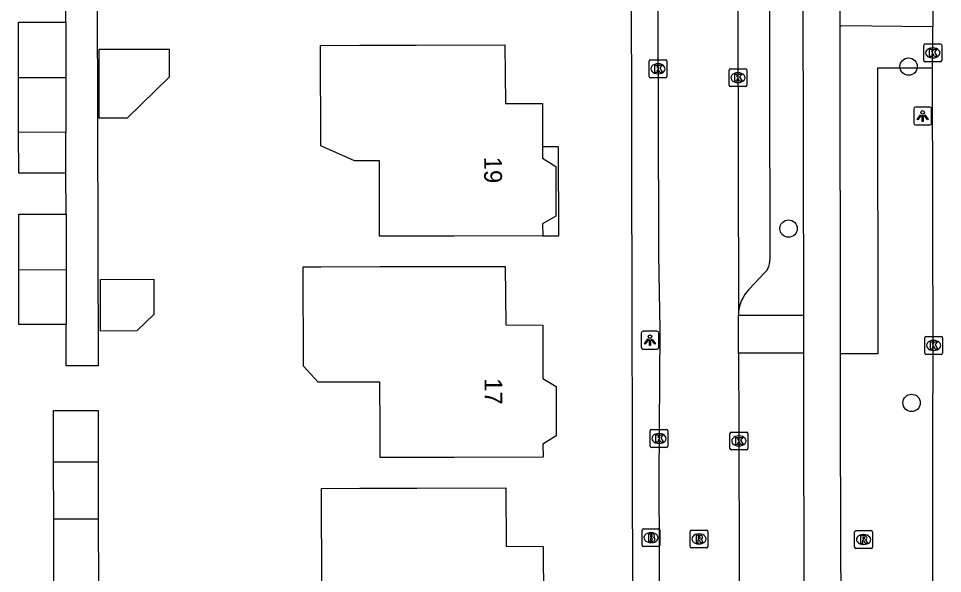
# Model space of a CAD drawing. Extents: x 160457 to 162082, y 388340 to 389736.
# Drawn here: x 160980.8 to 161032.8, y 388491.8 to 388523.1 of the extents above; entities that cross this region are included whole.
import ezdxf

# ---------------------------------------------------------------- set-up
doc = ezdxf.new("R2010")
doc.units = 0
for name, color, linetype in [('IMGEO_Boom', 7, 'Continuous'), ('IMGEO_Brandkraan', 7, 'Continuous'), ('IMGEO_Fietspad_gesloten', 7, 'Continuous'), ('IMGEO_Fietspad_open', 7, 'Continuous'), ('IMGEO_Kolk', 7, 'Continuous'), ('IMGEO_Lichtpunt', 7, 'Continuous'), ('IMGEO_Pand', 7, 'Continuous'), ('IMGEO_Pand_nummerreeks', 7, 'Continuous'), ('IMGEO_Pand_overbouw', 7, 'Continuous'), ('IMGEO_Parkeervlak_open', 7, 'Continuous'), ('IMGEO_Rijbaan_lokaal_gesloten', 7, 'Continuous'), ('IMGEO_Rijbaan_lokaal_open', 7, 'Continuous'), ('IMGEO_Rioolput', 7, 'Continuous'), ('IMGEO_Voetpad_open', 7, 'Continuous')]:
    doc.layers.add(name, color=color, linetype=linetype)

msp = doc.modelspace()

# ---------------------------------------------------------------- linework, layer by layer
at = {"layer": 'IMGEO_Boom'}
for centre in [(161030.855, 388520.352), (161024.103, 388511.242), (161031.022, 388501.444)]:
    msp.add_circle(centre, 0.489, dxfattribs=at)
at = {"layer": 'IMGEO_Brandkraan'}
for p, q in [((161015.872, 388493.436), (161015.872, 388494.288)), ((161015.947, 388494.362), (161016.799, 388494.362)), ((161016.36, 388494.142), (161016.385, 388494.142)), ((161016.873, 388494.288), (161016.873, 388493.436)), ((161016.799, 388493.362), (161015.947, 388493.362)), ((161016.383, 388493.582), (161016.358, 388493.582))]:
    msp.add_line(p, q, dxfattribs=at)
for points in [[(161015.872, 388493.436), (161015.872, 388494.288)], [(161015.947, 388494.362), (161016.799, 388494.362)], [(161016.873, 388494.288), (161016.873, 388493.436)], [(161016.22, 388494.062), (161016.22, 388493.662), (161016.433, 388493.662)], [(161016.451, 388494.062), (161016.22, 388494.062)], [(161016.399, 388493.981), (161016.345, 388493.981), (161016.345, 388493.905)], [(161016.345, 388493.905), (161016.398, 388493.905)], [(161016.407, 388493.829), (161016.345, 388493.829), (161016.345, 388493.748)], [(161016.345, 388493.748), (161016.407, 388493.748)], [(161016.799, 388493.362), (161015.947, 388493.362)]]:
    msp.add_lwpolyline(points, dxfattribs=at)
for centre, radius, start, end in [((161015.949, 388494.286), 0.0765, 91.552, 178.448), ((161015.949, 388494.286), 0.0765, 91.552, 178.448), ((161016.797, 388494.286), 0.0765, 1.552, 88.448), ((161016.797, 388494.286), 0.0765, 1.552, 88.448), ((161016.4, 388493.943), 0.0379, 267.8285, 90.9355), ((161016.408, 388493.788), 0.0404, 269.8759, 90.5077), ((161016.439, 388493.913), 0.251, 268.6676, 293.5347), ((161016.455, 388493.917), 0.145, 59.4692, 91.5367), ((161016.48, 388493.964), 0.0922, 285.5137, 58.1501), ((161016.485, 388493.772), 0.105, 301.3115, 78.989), ((161015.949, 388493.438), 0.0765, 181.552, 268.448), ((161015.949, 388493.438), 0.0765, 181.552, 268.448), ((161016.797, 388493.438), 0.0765, 271.552, 358.448), ((161016.797, 388493.438), 0.0765, 271.552, 358.448)]:
    msp.add_arc(centre, radius, start, end, dxfattribs=at)
for centre, major_axis, ratio, start_param, end_param in [((161016.359, 388493.862), (-0.387, 0.002), 0.722429, 4.712389, 7.853982), ((161016.384, 388493.862), (-0.39, 0.002), 0.717154, 1.570796, 4.712389)]:
    msp.add_ellipse(centre, major_axis=major_axis, ratio=ratio, start_param=start_param, end_param=end_param, dxfattribs=at)
at = {"layer": 'IMGEO_Fietspad_gesloten'}
for points in [[(161024.704, 388621.181), (161024.714, 388616.416), (161024.95, 388506.373)], [(161027, 388522.588), (161026.975, 388527.496)], [(161027.02, 388504.221), (161027, 388522.563), (161027, 388522.588)], [(161024.95, 388506.373), (161024.943, 388504.232)], [(161024.943, 388504.232), (161024.953, 388500), (161025.043, 388462.172)], [(161027.148, 388462.179), (161027.033, 388500), (161027.02, 388504.221)]]:
    msp.add_lwpolyline(points, dxfattribs=at)
at = {"layer": 'IMGEO_Fietspad_open'}
msp.add_lwpolyline([(161032.211, 388522.593), (161027.085, 388522.641), (161027.05, 388522.642)], dxfattribs=at)
msp.add_arc((161027.057, 388522.585), 0.0572, 97.1712, 177.234, dxfattribs=at)
at = {"layer": 'IMGEO_Kolk'}
for p, q in [((161031.714, 388520.698), (161031.714, 388521.55)), ((161031.789, 388521.624), (161032.641, 388521.624)), ((161032.202, 388521.404), (161032.227, 388521.404)), ((161032.715, 388521.55), (161032.715, 388520.698)), ((161016.265, 388519.803), (161016.265, 388520.655)), ((161016.34, 388520.729), (161017.192, 388520.729)), ((161017.266, 388520.655), (161017.266, 388519.803)), ((161032.225, 388520.844), (161032.2, 388520.844)), ((161016.753, 388520.509), (161016.778, 388520.509)), ((161020.755, 388519.304), (161020.755, 388520.156)), ((161020.83, 388520.23), (161021.682, 388520.23)), ((161021.756, 388520.156), (161021.756, 388519.304)), ((161032.641, 388520.624), (161031.789, 388520.624)), ((161017.192, 388519.729), (161016.34, 388519.729)), ((161016.776, 388519.949), (161016.751, 388519.949)), ((161021.243, 388520.01), (161021.268, 388520.01)), ((161021.682, 388519.23), (161020.83, 388519.23)), ((161021.266, 388519.45), (161021.241, 388519.45)), ((161031.761, 388504.246), (161031.761, 388505.098)), ((161031.836, 388505.172), (161032.688, 388505.172)), ((161032.762, 388505.098), (161032.762, 388504.246)), ((161032.249, 388504.952), (161032.274, 388504.952)), ((161032.688, 388504.172), (161031.836, 388504.172)), ((161032.272, 388504.392), (161032.247, 388504.392)), ((161016.322, 388499.014), (161016.322, 388499.866)), ((161016.397, 388499.94), (161017.249, 388499.94)), ((161017.323, 388499.866), (161017.323, 388499.014)), ((161016.81, 388499.72), (161016.835, 388499.72)), ((161020.81, 388498.878), (161020.81, 388499.73)), ((161020.885, 388499.804), (161021.737, 388499.804)), ((161021.298, 388499.584), (161021.323, 388499.584)), ((161021.811, 388499.73), (161021.811, 388498.878)), ((161017.249, 388498.94), (161016.397, 388498.94)), ((161016.833, 388499.16), (161016.808, 388499.16)), ((161021.321, 388499.024), (161021.296, 388499.024)), ((161021.737, 388498.804), (161020.885, 388498.804))]:
    msp.add_line(p, q, dxfattribs=at)
for points in [[(161031.714, 388520.698), (161031.714, 388521.55)], [(161031.789, 388521.624), (161032.641, 388521.624)], [(161032.035, 388521.324), (161032.158, 388521.324), (161032.158, 388521.173), (161032.288, 388521.324), (161032.452, 388521.324), (161032.306, 388521.173), (161032.459, 388520.924), (161032.307, 388520.924), (161032.222, 388521.088), (161032.158, 388521.021), (161032.158, 388520.924), (161032.035, 388520.924), (161032.035, 388521.324)], [(161032.715, 388521.55), (161032.715, 388520.698)], [(161016.265, 388519.803), (161016.265, 388520.655)], [(161016.34, 388520.729), (161017.192, 388520.729)], [(161017.266, 388520.655), (161017.266, 388519.803)], [(161016.586, 388520.429), (161016.709, 388520.429), (161016.709, 388520.278), (161016.839, 388520.429), (161017.003, 388520.429), (161016.857, 388520.278), (161017.01, 388520.029), (161016.858, 388520.029), (161016.773, 388520.193), (161016.709, 388520.126), (161016.709, 388520.029), (161016.586, 388520.029), (161016.586, 388520.429)], [(161020.755, 388519.304), (161020.755, 388520.156)], [(161020.83, 388520.23), (161021.682, 388520.23)], [(161021.756, 388520.156), (161021.756, 388519.304)], [(161032.641, 388520.624), (161031.789, 388520.624)], [(161017.192, 388519.729), (161016.34, 388519.729)], [(161021.076, 388519.93), (161021.199, 388519.93), (161021.199, 388519.779), (161021.329, 388519.93), (161021.493, 388519.93), (161021.347, 388519.779), (161021.5, 388519.53), (161021.348, 388519.53), (161021.263, 388519.694), (161021.199, 388519.627), (161021.199, 388519.53), (161021.076, 388519.53), (161021.076, 388519.93)], [(161021.682, 388519.23), (161020.83, 388519.23)], [(161031.761, 388504.246), (161031.761, 388505.098)], [(161031.836, 388505.172), (161032.688, 388505.172)], [(161032.762, 388505.098), (161032.762, 388504.246)], [(161032.082, 388504.872), (161032.205, 388504.872), (161032.205, 388504.721), (161032.335, 388504.872), (161032.499, 388504.872), (161032.353, 388504.721), (161032.506, 388504.472), (161032.354, 388504.472), (161032.269, 388504.636), (161032.205, 388504.569), (161032.205, 388504.472), (161032.082, 388504.472), (161032.082, 388504.872)], [(161032.688, 388504.172), (161031.836, 388504.172)], [(161016.322, 388499.014), (161016.322, 388499.866)], [(161016.397, 388499.94), (161017.249, 388499.94)], [(161017.323, 388499.866), (161017.323, 388499.014)], [(161016.643, 388499.64), (161016.766, 388499.64), (161016.766, 388499.489), (161016.896, 388499.64), (161017.06, 388499.64), (161016.914, 388499.489), (161017.067, 388499.24), (161016.915, 388499.24), (161016.83, 388499.404), (161016.766, 388499.337), (161016.766, 388499.24), (161016.643, 388499.24), (161016.643, 388499.64)], [(161020.81, 388498.878), (161020.81, 388499.73)], [(161020.885, 388499.804), (161021.737, 388499.804)], [(161021.131, 388499.504), (161021.254, 388499.504), (161021.254, 388499.353), (161021.384, 388499.504), (161021.548, 388499.504), (161021.402, 388499.353), (161021.555, 388499.104), (161021.403, 388499.104), (161021.318, 388499.268), (161021.254, 388499.201), (161021.254, 388499.104), (161021.131, 388499.104), (161021.131, 388499.504)], [(161021.811, 388499.73), (161021.811, 388498.878)], [(161017.249, 388498.94), (161016.397, 388498.94)], [(161021.737, 388498.804), (161020.885, 388498.804)]]:
    msp.add_lwpolyline(points, dxfattribs=at)
for centre, start, end in [((161031.791, 388521.548), 91.552, 178.448), ((161031.791, 388521.548), 91.552, 178.448), ((161032.639, 388521.548), 1.552, 88.448), ((161032.639, 388521.548), 1.552, 88.448), ((161016.342, 388520.653), 91.552, 178.448), ((161016.342, 388520.653), 91.552, 178.448), ((161017.19, 388520.653), 1.552, 88.448), ((161017.19, 388520.653), 1.552, 88.448), ((161031.791, 388520.7), 181.552, 268.448), ((161031.791, 388520.7), 181.552, 268.448), ((161032.639, 388520.7), 271.552, 358.448), ((161032.639, 388520.7), 271.552, 358.448), ((161020.832, 388520.154), 91.552, 178.448), ((161020.832, 388520.154), 91.552, 178.448), ((161021.68, 388520.154), 1.552, 88.448), ((161021.68, 388520.154), 1.552, 88.448), ((161016.342, 388519.805), 181.552, 268.448), ((161016.342, 388519.805), 181.552, 268.448), ((161017.19, 388519.805), 271.552, 358.448), ((161017.19, 388519.805), 271.552, 358.448), ((161020.832, 388519.306), 181.552, 268.448), ((161020.832, 388519.306), 181.552, 268.448), ((161021.68, 388519.306), 271.552, 358.448), ((161021.68, 388519.306), 271.552, 358.448), ((161031.838, 388505.096), 91.552, 178.448), ((161031.838, 388505.096), 91.552, 178.448), ((161032.686, 388505.096), 1.552, 88.448), ((161032.686, 388505.096), 1.552, 88.448), ((161031.838, 388504.248), 181.552, 268.448), ((161031.838, 388504.248), 181.552, 268.448), ((161032.686, 388504.248), 271.552, 358.448), ((161032.686, 388504.248), 271.552, 358.448), ((161016.399, 388499.864), 91.552, 178.448), ((161016.399, 388499.864), 91.552, 178.448), ((161017.247, 388499.864), 1.552, 88.448), ((161017.247, 388499.864), 1.552, 88.448), ((161020.887, 388499.728), 91.552, 178.448), ((161020.887, 388499.728), 91.552, 178.448), ((161021.735, 388499.728), 1.552, 88.448), ((161021.735, 388499.728), 1.552, 88.448), ((161016.399, 388499.016), 181.552, 268.448), ((161016.399, 388499.016), 181.552, 268.448), ((161017.247, 388499.016), 271.552, 358.448), ((161017.247, 388499.016), 271.552, 358.448), ((161020.887, 388498.88), 181.552, 268.448), ((161020.887, 388498.88), 181.552, 268.448), ((161021.735, 388498.88), 271.552, 358.448), ((161021.735, 388498.88), 271.552, 358.448)]:
    msp.add_arc(centre, 0.0765, start, end, dxfattribs=at)
for centre, major_axis, ratio, start_param, end_param in [((161032.201, 388521.124), (-0.387, 0.002), 0.722429, 4.712389, 7.853982), ((161032.226, 388521.124), (-0.39, 0.002), 0.717154, 1.570796, 4.712389), ((161016.752, 388520.229), (-0.387, 0.002), 0.722429, 4.712389, 7.853982), ((161016.777, 388520.229), (-0.39, 0.002), 0.717154, 1.570796, 4.712389), ((161021.242, 388519.73), (-0.387, 0.002), 0.722429, 4.712389, 7.853982), ((161021.267, 388519.73), (-0.39, 0.002), 0.717154, 1.570796, 4.712389), ((161032.248, 388504.672), (-0.387, 0.002), 0.722429, 4.712389, 7.853982), ((161032.273, 388504.672), (-0.39, 0.002), 0.717154, 1.570796, 4.712389), ((161016.809, 388499.44), (-0.387, 0.002), 0.722429, 4.712389, 7.853982), ((161016.834, 388499.44), (-0.39, 0.002), 0.717154, 1.570796, 4.712389), ((161021.297, 388499.304), (-0.387, 0.002), 0.722429, 4.712389, 7.853982), ((161021.322, 388499.304), (-0.39, 0.002), 0.717154, 1.570796, 4.712389)]:
    msp.add_ellipse(centre, major_axis=major_axis, ratio=ratio, start_param=start_param, end_param=end_param, dxfattribs=at)
at = {"layer": 'IMGEO_Lichtpunt'}
for p, q in [((161032.049, 388518.074), (161031.241, 388518.074)), ((161032.049, 388518.074), (161031.241, 388518.074)), ((161031.147, 388517.979), (161031.147, 388517.172)), ((161031.147, 388517.979), (161031.147, 388517.172)), ((161032.143, 388517.172), (161032.143, 388517.979)), ((161032.143, 388517.172), (161032.143, 388517.979)), ((161031.241, 388517.078), (161032.049, 388517.078)), ((161031.241, 388517.078), (161032.049, 388517.078)), ((161015.817, 388505.371), (161015.817, 388504.564)), ((161015.817, 388505.371), (161015.817, 388504.564)), ((161016.719, 388505.466), (161015.911, 388505.466)), ((161016.719, 388505.466), (161015.911, 388505.466)), ((161016.813, 388504.564), (161016.813, 388505.371)), ((161016.813, 388504.564), (161016.813, 388505.371)), ((161015.911, 388504.47), (161016.719, 388504.47)), ((161015.911, 388504.47), (161016.719, 388504.47))]:
    msp.add_line(p, q, dxfattribs=at)
for points in [[(161031.521, 388517.643), (161031.56, 388517.615), (161031.372, 388517.353), (161031.334, 388517.38), (161031.521, 388517.643)], [(161031.623, 388517.595), (161031.67, 388517.595), (161031.67, 388517.273), (161031.623, 388517.273), (161031.623, 388517.595)], [(161031.733, 388517.615), (161031.771, 388517.642), (161031.958, 388517.38), (161031.919, 388517.352), (161031.733, 388517.615)], [(161016.191, 388505.035), (161016.23, 388505.007), (161016.042, 388504.745), (161016.004, 388504.772), (161016.191, 388505.035)], [(161016.293, 388504.987), (161016.34, 388504.987), (161016.34, 388504.665), (161016.293, 388504.665), (161016.293, 388504.987)], [(161016.403, 388505.007), (161016.441, 388505.034), (161016.628, 388504.772), (161016.589, 388504.744), (161016.403, 388505.007)]]:
    msp.add_lwpolyline(points, dxfattribs=at)
for centre in [(161031.646, 388517.777), (161016.316, 388505.169)]:
    msp.add_circle(centre, 0.0994, dxfattribs=at)
for centre, start, end in [((161031.241, 388517.979), 90, 180), ((161031.241, 388517.979), 90, 180), ((161032.049, 388517.979), 0, 90), ((161032.049, 388517.979), 0, 90), ((161031.241, 388517.172), 180, 270), ((161031.241, 388517.172), 180, 270), ((161032.049, 388517.172), 270, 0), ((161032.049, 388517.172), 270, 360), ((161015.911, 388505.371), 90, 180), ((161015.911, 388505.371), 90, 180), ((161016.719, 388505.371), 0, 90), ((161016.719, 388505.371), 0, 90), ((161015.911, 388504.564), 180, 270), ((161015.911, 388504.564), 180, 270), ((161016.719, 388504.564), 270, 0), ((161016.719, 388504.564), 270, 360)]:
    msp.add_arc(centre, 0.0946, start, end, dxfattribs=at)
at = {"layer": 'IMGEO_Pand'}
for points in [[(160980.803, 388519.737), (160980.798, 388522.855), (160983.458, 388522.858)], [(160983.458, 388522.858), (160983.463, 388519.74)], [(160989.269, 388521.336), (160989.272, 388519.753), (160986.907, 388517.46), (160985.342, 388517.457), (160985.336, 388521.329), (160989.269, 388521.336)], [(161000, 388521.551), (161003.154, 388521.558), (161008.153, 388521.57), (161008.178, 388518.279), (161010.258, 388518.273), (161010.264, 388515.837), (161010.266, 388515.204), (161011.018, 388514.726), (161011.025, 388511.936), (161010.275, 388511.504), (161010.277, 388510.837), (161005.278, 388510.823), (161001.109, 388510.811), (161001.1, 388515.051), (161000, 388515.049), (160999.691, 388515.049), (160997.804, 388515.896), (160997.791, 388521.546), (161000, 388521.551)], [(160980.803, 388519.737), (160983.463, 388519.74)], [(160980.807, 388516.654), (160980.803, 388519.737)], [(160983.463, 388519.74), (160983.467, 388516.658)], [(160983.467, 388516.658), (160980.807, 388516.654)], [(160983.47, 388514.368), (160980.81, 388514.364), (160980.807, 388516.654)], [(160983.47, 388514.368), (160983.467, 388516.658)], [(160980.82, 388508.932), (160980.815, 388512.047), (160983.475, 388512.05)], [(160983.475, 388512.05), (160983.48, 388508.936)], [(160980.82, 388508.932), (160983.48, 388508.936)], [(160983.484, 388505.85), (160980.824, 388505.846), (160980.82, 388508.932)], [(160983.48, 388508.936), (160983.484, 388505.85)], [(161001.116, 388509.103), (161008.174, 388509.116), (161008.197, 388505.827), (161010.281, 388505.821), (161010.286, 388502.822), (161011.038, 388502.364), (161011.042, 388500), (161011.043, 388499.594), (161010.294, 388499.122), (161010.295, 388498.386), (161005.296, 388498.377), (161001.136, 388498.369), (161001.133, 388500), (161001.128, 388502.6), (160999.709, 388502.598), (160997.654, 388502.606), (160996.823, 388503.51), (160996.81, 388509.093), (160997.809, 388509.095), (161001.116, 388509.103)], [(160988.405, 388508.394), (160988.409, 388506.417), (160987.454, 388505.485), (160985.408, 388505.481), (160985.402, 388508.387), (160988.405, 388508.394)], [(160982.775, 388498.125), (160982.772, 388501.016), (160985.279, 388501.016), (160985.282, 388498.128)], [(160982.775, 388498.125), (160985.282, 388498.128)], [(160982.78, 388494.904), (160982.775, 388498.125)], [(160985.282, 388498.128), (160985.287, 388494.904)], [(161008.208, 388496.661), (161008.217, 388493.382), (161010.309, 388493.364), (161010.319, 388490.345), (161011.071, 388489.888), (161011.081, 388487.118), (161010.332, 388486.665), (161010.334, 388485.932), (161005.335, 388485.918), (161001.166, 388485.906), (161001.157, 388490.146), (161000, 388490.144), (160999.748, 388490.144), (160997.859, 388490.992), (160997.846, 388496.637), (161000, 388496.642), (161003.209, 388496.649), (161008.208, 388496.661)], [(160985.287, 388494.904), (160982.78, 388494.904)], [(160985.287, 388494.904), (160985.293, 388491.181), (160982.786, 388491.177), (160982.78, 388494.904)]]:
    msp.add_lwpolyline(points, dxfattribs=at)
at = {"layer": 'IMGEO_Pand_overbouw'}
msp.add_lwpolyline([(161010.277, 388510.837), (161011.178, 388510.837), (161011.162, 388515.845), (161010.264, 388515.837), (161010.266, 388515.204), (161011.018, 388514.726), (161011.025, 388511.936), (161010.275, 388511.504)], close=True, dxfattribs=at)
at = {"layer": 'IMGEO_Parkeervlak_open'}
for points in [[(161022.986, 388548.922), (161023.002, 388540.483), (161023.048, 388509.469)], [(161022.765, 388508.765), (161021.865, 388507.809)]]:
    msp.add_lwpolyline(points, dxfattribs=at)
for centre, radius, start, end in [((161022.188, 388509.406), 0.862, 312.0026, 4.1983), ((161023.377, 388506.347), 2.103, 135.9523, 175.1665)]:
    msp.add_arc(centre, radius, start, end, dxfattribs=at)
at = {"layer": 'IMGEO_Rijbaan_lokaal_gesloten'}
for points in [[(161032.194, 388527.118), (161032.214, 388522.986), (161032.211, 388522.593)], [(161032.193, 388520.283), (161032.211, 388522.593)], [(161032.004, 388475.58), (161032.208, 388481.936), (161032.227, 388500), (161032.231, 388503.917), (161032.193, 388520.283)]]:
    msp.add_lwpolyline(points, dxfattribs=at)
at = {"layer": 'IMGEO_Rijbaan_lokaal_open'}
for points in [[(161016.702, 388548.912), (161016.705, 388546.804), (161016.718, 388542.707), (161016.738, 388534.213), (161016.723, 388530.311), (161016.749, 388522.452), (161016.777, 388518.23), (161016.782, 388509.772), (161016.857, 388505.543), (161016.827, 388500), (161016.812, 388497.114), (161016.826, 388493.013), (161016.848, 388484.613), (161016.867, 388480.625), (161016.875, 388465.995)], [(161021.2, 388548.919), (161021.221, 388540.482), (161021.281, 388506.524)], [(161021.281, 388506.524), (161021.281, 388506.384)], [(161021.289, 388504.243), (161021.281, 388506.384)], [(161021.289, 388504.243), (161021.304, 388500), (161021.377, 388467.669), (161021.401, 388466.075)]]:
    msp.add_lwpolyline(points, dxfattribs=at)
at = {"layer": 'IMGEO_Rioolput'}
for p, q in [((161018.567, 388493.365), (161018.567, 388494.217)), ((161018.642, 388494.291), (161019.494, 388494.291)), ((161019.568, 388494.217), (161019.568, 388493.365)), ((161027.821, 388493.334), (161027.821, 388494.186)), ((161027.896, 388494.26), (161028.748, 388494.26)), ((161028.822, 388494.186), (161028.822, 388493.334)), ((161019.055, 388494.071), (161019.08, 388494.071)), ((161028.309, 388494.04), (161028.334, 388494.04)), ((161019.494, 388493.291), (161018.642, 388493.291)), ((161019.078, 388493.511), (161019.053, 388493.511)), ((161028.748, 388493.26), (161027.896, 388493.26)), ((161028.332, 388493.48), (161028.307, 388493.48))]:
    msp.add_line(p, q, dxfattribs=at)
for points in [[(161018.567, 388493.365), (161018.567, 388494.217)], [(161018.642, 388494.291), (161019.494, 388494.291)], [(161019.568, 388494.217), (161019.568, 388493.365)], [(161027.821, 388493.334), (161027.821, 388494.186)], [(161027.896, 388494.26), (161028.748, 388494.26)], [(161028.822, 388494.186), (161028.822, 388493.334)], [(161019.156, 388493.989), (161018.904, 388493.991), (161018.904, 388493.591)], [(161018.904, 388493.591), (161019.028, 388493.591), (161019.028, 388493.753), (161019.039, 388493.753)], [(161019.082, 388493.91), (161019.028, 388493.91), (161019.028, 388493.829)], [(161019.028, 388493.829), (161019.08, 388493.829)], [(161019.086, 388493.724), (161019.157, 388493.591), (161019.297, 388493.591), (161019.232, 388493.717)], [(161028.41, 388493.958), (161028.158, 388493.96), (161028.158, 388493.56)], [(161028.158, 388493.56), (161028.282, 388493.56), (161028.282, 388493.722), (161028.293, 388493.722)], [(161028.336, 388493.879), (161028.282, 388493.879), (161028.282, 388493.798)], [(161028.282, 388493.798), (161028.334, 388493.798)], [(161028.34, 388493.693), (161028.411, 388493.56), (161028.551, 388493.56), (161028.486, 388493.686)], [(161019.494, 388493.291), (161018.642, 388493.291)], [(161028.748, 388493.26), (161027.896, 388493.26)]]:
    msp.add_lwpolyline(points, dxfattribs=at)
for centre, radius, start, end in [((161018.644, 388494.215), 0.0765, 91.552, 178.448), ((161018.644, 388494.215), 0.0765, 91.552, 178.448), ((161019.492, 388494.215), 0.0765, 1.552, 88.448), ((161019.492, 388494.215), 0.0765, 1.552, 88.448), ((161027.898, 388494.184), 0.0765, 91.552, 178.448), ((161027.898, 388494.184), 0.0765, 91.552, 178.448), ((161028.746, 388494.184), 0.0765, 1.552, 88.448), ((161028.746, 388494.184), 0.0765, 1.552, 88.448), ((161019.038, 388493.7), 0.0533, 26.0293, 88.6989), ((161019.064, 388494.018), 0.19, 274.7715, 282.9687), ((161019.088, 388493.814), 0.0964, 77.0061, 93.1865), ((161019.102, 388493.871), 0.0378, 276.6634, 79.6772), ((161019.155, 388493.879), 0.109, 350.3612, 89.416), ((161019.153, 388493.879), 0.112, 277.5842, 350.9817), ((161019.137, 388493.664), 0.108, 29.5134, 73.7905), ((161028.292, 388493.669), 0.0533, 26.0293, 88.6989), ((161028.318, 388493.987), 0.19, 274.7715, 282.9687), ((161028.342, 388493.783), 0.0964, 77.0061, 93.1865), ((161028.356, 388493.84), 0.0378, 276.6634, 79.6772), ((161028.409, 388493.848), 0.109, 350.3612, 89.416), ((161028.407, 388493.848), 0.112, 277.5842, 350.9817), ((161028.391, 388493.633), 0.108, 29.5134, 73.7905), ((161018.644, 388493.367), 0.0765, 181.552, 268.448), ((161018.644, 388493.367), 0.0765, 181.552, 268.448), ((161019.492, 388493.367), 0.0765, 271.552, 358.448), ((161019.492, 388493.367), 0.0765, 271.552, 358.448), ((161027.898, 388493.336), 0.0765, 181.552, 268.448), ((161027.898, 388493.336), 0.0765, 181.552, 268.448), ((161028.746, 388493.336), 0.0765, 271.552, 358.448), ((161028.746, 388493.336), 0.0765, 271.552, 358.448)]:
    msp.add_arc(centre, radius, start, end, dxfattribs=at)
for centre, major_axis, ratio, start_param, end_param in [((161019.054, 388493.791), (-0.387, 0.002), 0.722429, 4.712389, 7.853982), ((161019.079, 388493.791), (-0.39, 0.002), 0.717154, 1.570796, 4.712389), ((161028.308, 388493.76), (-0.387, 0.002), 0.722429, 4.712389, 7.853982), ((161028.333, 388493.76), (-0.39, 0.002), 0.717154, 1.570796, 4.712389)]:
    msp.add_ellipse(centre, major_axis=major_axis, ratio=ratio, start_param=start_param, end_param=end_param, dxfattribs=at)
at = {"layer": 'IMGEO_Voetpad_open'}
for points in [[(161015.378, 388466.056), (161015.323, 388500), (161015.314, 388505.844), (161015.227, 388546.422), (161008.109, 388546.416)], [(160985.186, 388538.067), (160985.273, 388503.533), (160983.484, 388503.529), (160983.484, 388505.85)], [(160983.458, 388522.858), (160983.452, 388527.449)], [(161027.02, 388504.221), (161029.136, 388504.228), (161029.121, 388520.276), (161032.193, 388520.283)], [(160983.475, 388512.05), (160983.47, 388514.368)], [(161021.281, 388506.384), (161024.95, 388506.373)], [(161024.943, 388504.232), (161021.289, 388504.243)]]:
    msp.add_lwpolyline(points, dxfattribs=at)

# ---------------------------------------------------------------- texts
at = {"layer": 'IMGEO_Pand_nummerreeks'}
for s, rotation, p in [('19', 270.1464, (161006.986, 388515.282)), ('17', 270.1079, (161007.006, 388502.832))]:
    msp.add_text(s, height=1, rotation=rotation, dxfattribs=at).set_placement(p)

doc.saveas('drawing.dxf')
